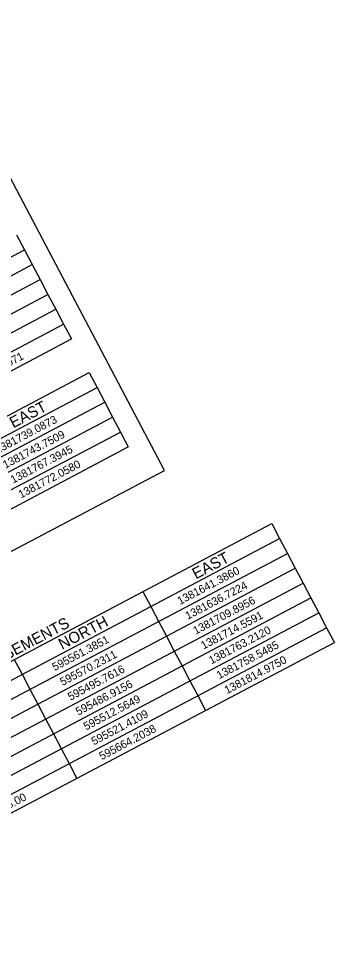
# Model space of a CAD drawing. Extents: x 1379448 to 1382868, y 593769 to 596827.
# Drawn here: x 1382473 to 1382868, y 594560 to 595724 of the extents above; entities that cross this region are included whole.
import ezdxf

# ---------------------------------------------------------------- set-up
doc = ezdxf.new("R2010")
doc.units = 0
for name, color, linetype in [('CTL Sheet Border CELL', 7, 'Continuous'), ('CTL Sheet Notes CELL', 7, 'Continuous'), ('CTL Sheet Table Cell', 7, 'Continuous'), ('CTL Sheet Text', 7, 'Continuous'), ('Scratch_Level_8', 7, 'Continuous')]:
    doc.layers.add(name, color=color, linetype=linetype)

msp = doc.modelspace()

# ---------------------------------------------------------------- linework, layer by layer
at = {"layer": 'CTL Sheet Border CELL'}
msp.add_lwpolyline([(1381803.8, 596774.4), (1379496.1, 595557.9), (1380347.7, 593942.5), (1382655.4, 595159.1)], close=True, dxfattribs=at)
at = {"layer": 'CTL Sheet Table Cell'}
for p, q in [((1382470.4, 595453.4), (1382480.2, 595434.8)), ((1381786.7, 595069.2), (1382480.2, 595434.8)), ((1382480.2, 595434.8), (1382490, 595416.2)), ((1381796.5, 595050.6), (1382490, 595416.2)), ((1382490, 595416.2), (1382499.8, 595397.7)), ((1381806.3, 595032), (1382499.8, 595397.7)), ((1382499.8, 595397.7), (1382509.6, 595379.1)), ((1381816.1, 595013.5), (1382509.6, 595379.1)), ((1382509.6, 595379.1), (1382519.4, 595360.5)), ((1381825.9, 594994.9), (1382519.4, 595360.5)), ((1382519.4, 595360.5), (1382529.2, 595341.9)), ((1381835.7, 594976.3), (1382529.2, 595341.9)), ((1382529.2, 595341.9), (1382539, 595323.4)), ((1381845.5, 594957.7), (1382539, 595323.4)), ((1381867.6, 594915.7), (1382561.2, 595281.3)), ((1382561.2, 595281.3), (1382571, 595262.7)), ((1381877.4, 594897.1), (1382571, 595262.7)), ((1382571, 595262.7), (1382580.7, 595244.2)), ((1381887.2, 594878.5), (1382580.7, 595244.2)), ((1382580.7, 595244.2), (1382590.5, 595225.6)), ((1381897, 594860), (1382590.5, 595225.6)), ((1382590.5, 595225.6), (1382600.3, 595207)), ((1381906.8, 594841.4), (1382600.3, 595207)), ((1382600.3, 595207), (1382610.1, 595188.4)), ((1381916.6, 594822.8), (1382610.1, 595188.4))]:
    msp.add_line(p, q, dxfattribs=at)
at = {"layer": 'Scratch_Level_8'}
for p, q in [((1382095.9, 594726.9), (1382789.4, 595092.5)), ((1382789.4, 595092.5), (1382799.2, 595073.9)), ((1382105.7, 594708.3), (1382799.2, 595073.9)), ((1382799.2, 595073.9), (1382809, 595055.3)), ((1382115.5, 594689.7), (1382809, 595055.3)), ((1382809, 595055.3), (1382818.8, 595036.8)), ((1382125.3, 594671.1), (1382818.8, 595036.8)), ((1382818.8, 595036.8), (1382828.6, 595018.2)), ((1382135.1, 594652.6), (1382828.6, 595018.2)), ((1382828.6, 595018.2), (1382838.4, 594999.6)), ((1382628.4, 595007.6), (1382638.2, 594989)), ((1382144.9, 594634), (1382838.4, 594999.6)), ((1382838.4, 594999.6), (1382848.2, 594981)), ((1382638.2, 594989), (1382648, 594970.5)), ((1382154.6, 594615.4), (1382848.2, 594981)), ((1382848.2, 594981), (1382858, 594962.4)), ((1382164.4, 594596.8), (1382858, 594962.4)), ((1382648, 594970.5), (1382657.8, 594951.9)), ((1382858, 594962.4), (1382867.8, 594943.9)), ((1382657.8, 594951.9), (1382667.6, 594933.3)), ((1382174.2, 594578.3), (1382867.8, 594943.9)), ((1382667.6, 594933.3), (1382677.4, 594914.7)), ((1382467.4, 594922.7), (1382477.2, 594904.2)), ((1382677.4, 594914.7), (1382687.2, 594896.1)), ((1382477.2, 594904.2), (1382487, 594885.6)), ((1382687.2, 594896.1), (1382697, 594877.6)), ((1382487, 594885.6), (1382496.8, 594867)), ((1382496.8, 594867), (1382506.6, 594848.4)), ((1382697, 594877.6), (1382706.8, 594859)), ((1382506.6, 594848.4), (1382516.4, 594829.8)), ((1382516.4, 594829.8), (1382526.2, 594811.3)), ((1382526.2, 594811.3), (1382536, 594792.7)), ((1382536, 594792.7), (1382545.8, 594774.1))]:
    msp.add_line(p, q, dxfattribs=at)

# ---------------------------------------------------------------- texts
at = {"layer": 'CTL Sheet Notes CELL'}
msp.add_text('EAST', height=14, rotation=27.7977, dxfattribs=at).set_placement((1382466.3, 595211.5))
at = {"layer": 'CTL Sheet Text'}
for s, p in [('1381921.4071', (1382404.7, 595258.8)), ('1381739.0873', (1382446.5, 595179.6)), ('1381743.7509', (1382456.3, 595161)), ('1381767.3945', (1382466.1, 595142.4)), ('1381772.0580', (1382475.9, 595123.9))]:
    msp.add_text(s, height=10, rotation=27.7977, dxfattribs=at).set_placement(p)
at = {"layer": 'Scratch_Level_8'}
for s, height, p in [('EAST', 14, (1382694.6, 595022.7)), ('1381641.3860', 10, (1382674.7, 594990.8)), ('1381636.7224', 10, (1382684.5, 594972.2)), ('1381709.8956', 10, (1382694.3, 594953.6)), ('TEMPORARY EASEMENTS', 14, (1382326.3, 594852.3)), ('NORTH', 14, (1382527.4, 594934.6)), ('1381714.5591', 10, (1382704.1, 594935)), ('1381763.2120', 10, (1382713.9, 594916.5)), ('595561.3851', 10, (1382518.1, 594908.2)), ('1381758.5485', 10, (1382723.7, 594897.9)), ('595570.2311', 10, (1382527.9, 594889.6)), ('1381814.9750', 10, (1382733.5, 594879.3)), ('595495.7616', 10, (1382537.7, 594871.1)), ('595486.9156', 10, (1382547.5, 594852.5)), ('595512.5649', 10, (1382557.3, 594833.9)), ('595521.4109', 10, (1382567.1, 594815.3)), ('595664.2038', 10, (1382576.9, 594796.7)), ('-45.00', 10, (1382450.2, 594730))]:
    msp.add_text(s, height=height, rotation=27.7977, dxfattribs=at).set_placement(p)

doc.saveas('drawing.dxf')
